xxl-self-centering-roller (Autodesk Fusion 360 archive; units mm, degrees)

design "XXL SELF CENTERING ROLLER" references "XXL ROLLER"
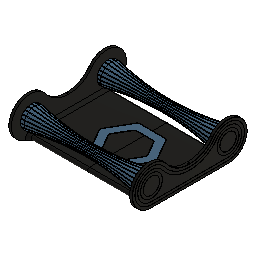
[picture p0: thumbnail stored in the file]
sketch "Sketch1" plane through (0, 0, 0) normal (1, 0, 0) x axis (0, 1, 0)
  line L1 (70, 4) -> (-70, 4)
  line L2 (70, -4) -> (70, 4)
  line L3 (-70, -4) -> (70, -4)
  line L4 (-70, 4) -> (-70, -4)
  line L5 (70, -4) -> (-70, 4)
  line L6 (-70, -4) -> (70, 4)
  line L7 (-110.4145, 0) -> (-90.2073, 35)
  line L8 (-90.2073, -35) -> (-110.4145, 0)
  line L9 (-49.7927, -35) -> (-90.2073, -35)
  line L10 (-29.5855, 0) -> (-49.7927, -35)
  line L11 (-49.7927, 35) -> (-29.5855, 0)
  line L12 (-90.2073, 35) -> (-49.7927, 35)
  line L13 (29.5855, 0) -> (49.7927, 35)
  line L14 (49.7927, -35) -> (29.5855, 0)
  line L15 (90.2073, -35) -> (49.7927, -35)
  line L16 (110.4145, 0) -> (90.2073, -35)
  line L17 (90.2073, 35) -> (110.4145, 0)
  line L18 (49.7927, 35) -> (90.2073, 35)
  line L19 (-49.7927, -35) -> (49.7927, -35)
  line L20 (29.5855, 0) -> (-29.5855, 0)
  line L21 (-85.5885, -27) -> (-90.2073, -35)
  line L22 (85.5885, -27) -> (-85.5885, -27)
  line L23 (90.2073, -35) -> (85.5885, -27)
  line L24 (-94.8261, -27) -> (94.8261, -27)
  line L25 (70, 0) -> (-70, 0)
  line L26 (0, -35) -> (0, 0)
  line L27 (0, -35) -> (0, -27)
  line L28 (-70, -27) -> (70, -27)
  line L29 (70, -35) -> (-70, -35)
  line L30 (70, -31) -> (70, 0)
  circle C1 centre (-70, 0) radius 4
  circle C2 centre (70, 0) radius 4
  circle C3 centre (70, 0) radius 5
  circle C4 centre (-70, 0) radius 5
  circle C5 centre (-70, 0) radius 35
  circle C6 centre (70, 0) radius 35
  arc A1 centre (-70, -31) radius 4 clockwise from (-70, -35) to (-70, -27)
  arc A2 centre (70, -31) radius 4 clockwise from (70, -27) to (70, -35)
  point P6 (0, 0)
  point P1 (0, 0)
  point P7 (-70, 0)
  point P8 (70, 0)
  point P15 (-70, 0)
  point P22 (70, 0)
  point P27 (94.8261, -27)
  point P28 (-94.8261, -27)
  point P29 (-70, 0)
  point P31 (-70, 0)
  point P32 (70, 0)
  point P33 (0, 0)
  point P34 (0, -35)
  point P35 (0, -27)
  point P42 (0, -31)
  point P30 (70, 0)
  point P43 (70, 0)
  point P40 (70, -31)
  point P44 (70, -31)
  point P41 (-70, -31)
  point P4 (70, -4)
  point P5 (-70, -4)
  horizontal L1
  perpendicular L1 L2
  parallel L1 L3
  parallel L2 L4
  coincident L5 P6
  coincident L6 P6
  coincident P1 P6
  midpoint L4 P7
  midpoint L2 P8
  tangent L1 C1
  coincident P7 P15
  coincident P8 P22
  horizontal L12
  horizontal L18
  parallel L15 L22
  parallel L17 L23
  parallel L7 L21
  coincident L16 P27
  coincident L8 P28
  parallel L22 L24
  collinear L22 L24
  concentric C1 C5
  tangent L9 C5
  concentric C2 C6
  tangent L15 C6
  coincident P29 P31
  coincident P22 P32
  coincident P6 P33
  midpoint L19 P34
  midpoint L24 P35
  tangent L28 A1
  tangent A1 L29
  parallel L28 L29
  tangent L29 A2
  tangent L28 A2
  midpoint L27 P42
  coincident P30 P43
  coincident P40 P44
  vertical L30
  collinear L22 L28
  collinear L19 L29
  vertical P29 P41
  dimension "d1" diameter C1 = 8 (= "d2")
  dimension "d2" diameter C2 = 8
  dimension "d3" distance P4 P5 = 140
  dimension "d4" distance L9 L12 = 70
  dimension "d5" distance L15 L18 = 70 (= "d4")
  dimension "d6" distance L19 L22 = 8
  dimension "d13" = 1
  dimension "d14" = 1
extrude "Extrude1" new body sketch "MirrorComponent4" profile of L9 L10 L14 L15 L19 L22 L24 C5 C6 L27 L28 A1 L29 A2 against normal blind 108
extrude "Extrude2" add sketch "MirrorComponent4" profile of L1 L2 L3 L4 C1 C2 L9 L10 L14 L15 L19 L20 L21 L22 L23 C3 C4 L24 C5 C6 L25 L27 L28 A1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 along normal blind 5
fillet "Fillet3" radius 50
extrude "Extrude3" add sketch "MirrorComponent4" profile of L2 L4 C1 C2 against normal blind 6
chamfer "Chamfer1" distance 0.6
sketch "Sketch2" plane through (5, 0, 0) normal (1, 0, 0) x axis (0, 1, 0)
  line L1 (63.8564, -25) -> (-63.8564, -25)
  line L2 (78.5788, -0.5) -> (64.7224, -24.5)
  line L3 (64.7224, 24.5) -> (78.5788, 0.5)
  line L4 (36.1436, 25) -> (63.8564, 25)
  line L5 (21.4212, 0.5) -> (35.2776, 24.5)
  line L6 (-20.5551, 0) -> (20.5551, 0)
  line L7 (-35.2776, 24.5) -> (-21.4212, 0.5)
  line L8 (-63.8564, 25) -> (-36.1436, 25)
  line L9 (-78.5788, 0.5) -> (-64.7224, 24.5)
  line L10 (-64.7224, -24.5) -> (-78.5788, -0.5)
  line L11 (-75.8653, 0) -> (-62.9326, 22.4)
  line L12 (-62.9326, -22.4) -> (-75.8653, 0)
  line L13 (-35.5662, -22.4) -> (-62.9326, -22.4)
  line L14 (62.9326, -22.4) -> (-35.5662, -22.4)
  line L15 (75.8653, 0) -> (62.9326, -22.4)
  line L16 (62.9326, 22.4) -> (75.8653, 0)
  line L17 (37.0674, 22.4) -> (62.9326, 22.4)
  line L18 (23.6728, -0.8) -> (37.0674, 22.4)
  line L19 (-20.5551, -2.6) -> (20.5551, -2.6)
  line L20 (-37.0674, 22.4) -> (-23.6728, -0.8)
  line L21 (-62.9326, 22.4) -> (-37.0674, 22.4)
  line L22 (-73.5559, 0) -> (-61.7779, 20.4)
  line L23 (-61.7779, -20.4) -> (-73.5559, 0)
  line L24 (-35.5662, -20.4) -> (-61.7779, -20.4)
  line L25 (61.7779, -20.4) -> (-35.5662, -20.4)
  line L26 (73.5559, 0) -> (61.7779, -20.4)
  line L27 (61.7779, 20.4) -> (73.5559, 0)
  line L28 (38.2221, 20.4) -> (61.7779, 20.4)
  line L29 (25.4049, -1.8) -> (38.2221, 20.4)
  line L30 (-20.5551, -4.6) -> (20.5551, -4.6)
  line L31 (-38.2221, 20.4) -> (-25.4049, -1.8)
  line L32 (-61.7779, 20.4) -> (-38.2221, 20.4)
  line L33 (70, -35) -> (-70, -35)
  line L34 (-1.2614, 0) -> (1.2614, 0)
  arc A1 centre (-63.8564, -24) radius 1 clockwise from (-63.8564, -25) to (-64.7224, -24.5)
  arc A2 centre (63.8564, -24) radius 1 clockwise from (64.7224, -24.5) to (63.8564, -25)
  arc A3 centre (77.7128, 0) radius 1 clockwise from (78.5788, 0.5) to (78.5788, -0.5)
  arc A4 centre (63.8564, 24) radius 1 clockwise from (63.8564, 25) to (64.7224, 24.5)
  arc A5 centre (36.1436, 24) radius 1 clockwise from (35.2776, 24.5) to (36.1436, 25)
  arc A6 centre (20.5551, 1) radius 1 clockwise from (21.4212, 0.5) to (20.5551, 0)
  arc A7 centre (-20.5551, 1) radius 1 clockwise from (-20.5551, 0) to (-21.4212, 0.5)
  arc A8 centre (-36.1436, 24) radius 1 clockwise from (-36.1436, 25) to (-35.2776, 24.5)
  arc A9 centre (-63.8564, 24) radius 1 clockwise from (-64.7224, 24.5) to (-63.8564, 25)
  arc A10 centre (-77.7128, 0) radius 1 clockwise from (-78.5788, -0.5) to (-78.5788, 0.5)
  arc A11 centre (20.5551, 1) radius 3.6 clockwise from (23.6728, -0.8) to (20.5551, -2.6)
  arc A12 centre (-20.5551, 1) radius 3.6 clockwise from (-20.5551, -2.6) to (-23.6728, -0.8)
  arc A13 centre (20.5551, 1) radius 5.6 clockwise from (25.4049, -1.8) to (20.5551, -4.6)
  arc A14 centre (-20.5551, 1) radius 5.6 clockwise from (-20.5551, -4.6) to (-25.4049, -1.8)
  arc A15 centre (70, 0) radius 35 clockwise from (41.6959, 20.5882) to (70, -35)
  arc A16 centre (-70, 0) radius 35 clockwise from (-70, -35) to (-41.6959, 20.5882)
  arc A17 centre (-1.2614, 50) radius 50 clockwise from (-1.2614, 0) to (-41.6959, 20.5882)
  arc A18 centre (1.2614, 50) radius 50 clockwise from (41.6959, 20.5882) to (1.2614, 0)
  concentric A6 A11
  concentric A7 A12
  tangent A12 L20
  tangent L18 A11
  tangent A11 L19
  tangent L19 A12
  concentric A6 A13
  concentric A7 A14
  tangent A14 L31
  tangent A13 L30
  tangent L29 A13
  tangent L30 A14
sketch "Sketch3" plane through (0, 0, -27) normal (0, 0, 1) x axis (-1, 0, 0)
  line L1 (108, 70) -> (108, -70)
  line L2 (159.9615, 0) -> (133.9808, -45)
  line L3 (133.9808, 45) -> (159.9615, 0)
  line L4 (82.0192, 45) -> (133.9808, 45)
  line L5 (56.0385, 0) -> (82.0192, 45)
  line L6 (82.0192, -45) -> (56.0385, 0)
  line L7 (133.9808, -45) -> (82.0192, -45)
  line L8 (125.3205, 30) -> (142.641, 0)
  line L9 (90.6795, 30) -> (125.3205, 30)
  line L10 (73.359, 0) -> (90.6795, 30)
  line L11 (90.6795, -30) -> (73.359, 0)
  line L12 (125.3205, -30) -> (90.6795, -30)
  line L13 (142.641, 0) -> (125.3205, -30)
  line L14 (108, -70) -> (0, -70)
  line L15 (0, 70) -> (108, 70)
  line L16 (0, -70) -> (0, 70)
  point P12 (108, 0)
  midpoint L1 P12
  horizontal L7
  dimension "d23" distance L4 L7 = 90
  dimension "d24" = -15
extrude "Extrude5" cut sketch "Sketch3" profile of L1 L4 L5 L6 L7 L12 L10 L9 L11 against normal blind 2
fillet "Fillet2" radius 5
extrude "Extrude6" add sketch "MirrorComponent4" profile of L1 L3 C1 C2 C3 C4 against normal blind 1.4
chamfer "Chamfer3" distance 1.4
sketch "Sketch4" plane through (5, 0, 0) normal (1, 0, 0) x axis (0, 1, 0)
  line L1 (70, -35) -> (-70, -35)
  line L2 (-1.2614, 0) -> (1.2614, 0)
  line L3 (-1.2614, -5) -> (1.2614, -5)
  line L4 (70, -30) -> (-70, -30)
  line L5 (-1.2614, -10) -> (1.2614, -10)
  line L6 (70, -25) -> (-70, -25)
  arc A1 centre (-70, 0) radius 35 clockwise from (-70, -35) to (-41.6959, 20.5882)
  arc A2 centre (70, 0) radius 35 clockwise from (41.6959, 20.5882) to (70, -35)
  arc A3 centre (-1.2614, 50) radius 50 clockwise from (-1.2614, 0) to (-41.6959, 20.5882)
  circle C1 centre (-70, 0) radius 15
  circle C2 centre (70, 0) radius 20
  circle C3 centre (-70, 0) radius 20
  circle C4 centre (70, 0) radius 15
  arc A4 centre (1.2614, 50) radius 50 clockwise from (41.6959, 20.5882) to (1.2614, 0)
  arc A5 centre (70, 0) radius 30 clockwise from (45.7393, 17.6471) to (70, -30)
  arc A6 centre (1.2614, 50) radius 55 clockwise from (45.7393, 17.6471) to (1.2614, -5)
  arc A7 centre (-1.2614, 50) radius 55 clockwise from (-1.2614, -5) to (-45.7393, 17.6471)
  arc A8 centre (-70, 0) radius 30 clockwise from (-70, -30) to (-45.7393, 17.6471)
  arc A9 centre (70, 0) radius 25 clockwise from (49.7828, 14.7059) to (70, -25)
  arc A10 centre (1.2614, 50) radius 60 clockwise from (49.7828, 14.7059) to (1.2614, -10)
  arc A11 centre (-1.2614, 50) radius 60 clockwise from (-1.2614, -10) to (-49.7828, 14.7059)
  arc A12 centre (-70, 0) radius 25 clockwise from (-70, -25) to (-49.7828, 14.7059)
  concentric A1 C1
  concentric A2 C2
  concentric C1 C3
  concentric C2 C4
  concentric A2 A9
  concentric A4 A10
  concentric A3 A11
  concentric A1 A12
  tangent A11 A12
  tangent A9 A10
  tangent L5 A11
  tangent A10 L5
  tangent A9 L6
  tangent A12 L6
  dimension "d152" = -5
  dimension "d154" distance C3 A12 = 5
  dimension "d155" distance C1 C3 = 5
  dimension "d156" distance C2 A9 = 5
  dimension "d157" distance C2 C4 = 5
extrude "Extrude10" cut sketch "Sketch4" profile of C1 C2 C3 C4 A8 L3 A6 A7 L4 A5 A12 L5 A10 A11 A9 L6 against normal blind 0.4
chamfer "Chamfer6" distance 0.4
chamfer "Chamfer10" distance 5
mirror "Mirror1" mirrorStitchTolerance 0.1
sketch "Sketch1" plane through (0, 0, -29) normal (0, 0, 1) x axis (-1, 0, 0)
  line L1 (131.094, -45) -> (84.906, -45)
  line L2 (93.5662, -30) -> (122.4338, -30)
  line L3 (74.8024, -2.5) -> (89.2361, -27.5)
  line L4 (89.2361, 27.5) -> (74.8024, 2.5)
  line L5 (122.4338, 30) -> (93.5662, 30)
  line L6 (84.906, 45) -> (131.094, 45)
  line L7 (57.4819, 2.5) -> (80.5759, 42.5)
  line L8 (80.5759, -42.5) -> (57.4819, -2.5)
  line L9 (158.5181, -2.5) -> (135.4241, -42.5)
  line L10 (135.4241, 42.5) -> (158.5181, 2.5)
  line L11 (141.1976, 2.5) -> (126.7639, 27.5)
  line L12 (126.7639, -27.5) -> (141.1976, -2.5)
  line L13 (84.906, 45) -> (131.094, 45)
  line L14 (57.4819, 2.5) -> (80.5759, 42.5)
  line L15 (80.5759, -42.5) -> (57.4819, -2.5)
  line L16 (131.094, -45) -> (84.906, -45)
  line L17 (158.5181, -2.5) -> (135.4241, -42.5)
  line L18 (135.4241, 42.5) -> (158.5181, 2.5)
  line L19 (122.4338, 30) -> (93.5662, 30)
  line L20 (141.1976, 2.5) -> (126.7639, 27.5)
  line L21 (126.7639, -27.5) -> (141.1976, -2.5)
  line L22 (93.5662, -30) -> (122.4338, -30)
  line L23 (74.8024, -2.5) -> (89.2361, -27.5)
  line L24 (89.2361, 27.5) -> (74.8024, 2.5)
  line L25 (57.6551, 2.4) -> (80.7491, 42.4)
  line L26 (80.7491, -42.4) -> (57.6551, -2.4)
  line L27 (131.094, -44.8) -> (84.906, -44.8)
  line L28 (158.3449, -2.4) -> (135.2509, -42.4)
  line L29 (135.2509, 42.4) -> (158.3449, 2.4)
  line L30 (84.906, 44.8) -> (131.094, 44.8)
  line L31 (122.4338, 30.2) -> (93.5662, 30.2)
  line L32 (89.0629, 27.6) -> (74.6292, 2.6)
  line L33 (74.6292, -2.6) -> (89.0629, -27.6)
  line L34 (93.5662, -30.2) -> (122.4338, -30.2)
  line L35 (126.9371, -27.6) -> (141.3708, -2.6)
  line L36 (141.3708, 2.6) -> (126.9371, 27.6)
  line L37 (151.3013, 0) -> (129.6506, -37.5)
  line L38 (129.6506, 37.5) -> (151.3013, 0)
  line L39 (86.3494, 37.5) -> (129.6506, 37.5)
  line L40 (64.6987, 0) -> (86.3494, 37.5)
  line L41 (86.3494, -37.5) -> (64.6987, 0)
  line L42 (129.6506, -37.5) -> (86.3494, -37.5)
  arc A1 centre (84.906, -40) radius 5 clockwise from (84.906, -45) to (80.5759, -42.5)
  arc A2 centre (93.5662, -25) radius 5 clockwise from (93.5662, -30) to (89.2361, -27.5)
  arc A3 centre (79.1325, 0) radius 5 clockwise from (74.8024, -2.5) to (74.8024, 2.5)
  arc A4 centre (93.5662, 25) radius 5 clockwise from (89.2361, 27.5) to (93.5662, 30)
  arc A5 centre (84.906, 40) radius 5 clockwise from (80.5759, 42.5) to (84.906, 45)
  arc A6 centre (61.812, 0) radius 5 clockwise from (57.4819, -2.5) to (57.4819, 2.5)
  arc A7 centre (131.094, -40) radius 5 clockwise from (135.4241, -42.5) to (131.094, -45)
  arc A8 centre (154.188, 0) radius 5 clockwise from (158.5181, 2.5) to (158.5181, -2.5)
  arc A9 centre (131.094, 40) radius 5 clockwise from (131.094, 45) to (135.4241, 42.5)
  arc A10 centre (122.4338, 25) radius 5 clockwise from (122.4338, 30) to (126.7639, 27.5)
  arc A11 centre (136.8675, 0) radius 5 clockwise from (141.1976, 2.5) to (141.1976, -2.5)
  arc A12 centre (122.4338, -25) radius 5 clockwise from (126.7639, -27.5) to (122.4338, -30)
  arc A13 centre (84.906, 40) radius 5 clockwise from (80.5759, 42.5) to (84.906, 45)
  arc A14 centre (61.812, 0) radius 5 clockwise from (57.4819, -2.5) to (57.4819, 2.5)
  arc A15 centre (84.906, -40) radius 5 clockwise from (84.906, -45) to (80.5759, -42.5)
  arc A16 centre (131.094, -40) radius 5 clockwise from (135.4241, -42.5) to (131.094, -45)
  arc A17 centre (154.188, 0) radius 5 clockwise from (158.5181, 2.5) to (158.5181, -2.5)
  arc A18 centre (131.094, 40) radius 5 clockwise from (131.094, 45) to (135.4241, 42.5)
  arc A19 centre (122.4338, 25) radius 5 clockwise from (122.4338, 30) to (126.7639, 27.5)
  arc A20 centre (136.8675, 0) radius 5 clockwise from (141.1976, 2.5) to (141.1976, -2.5)
  arc A21 centre (122.4338, -25) radius 5 clockwise from (126.7639, -27.5) to (122.4338, -30)
  arc A22 centre (93.5662, -25) radius 5 clockwise from (93.5662, -30) to (89.2361, -27.5)
  arc A23 centre (79.1325, 0) radius 5 clockwise from (74.8024, -2.5) to (74.8024, 2.5)
  arc A24 centre (93.5662, 25) radius 5 clockwise from (89.2361, 27.5) to (93.5662, 30)
  arc A25 centre (61.812, 0) radius 4.8 clockwise from (57.6551, -2.4) to (57.6551, 2.4)
  arc A26 centre (84.906, -40) radius 4.8 clockwise from (84.906, -44.8) to (80.7491, -42.4)
  arc A27 centre (131.094, -40) radius 4.8 clockwise from (135.2509, -42.4) to (131.094, -44.8)
  arc A28 centre (154.188, 0) radius 4.8 clockwise from (158.3449, 2.4) to (158.3449, -2.4)
  arc A29 centre (131.094, 40) radius 4.8 clockwise from (131.094, 44.8) to (135.2509, 42.4)
  arc A30 centre (84.906, 40) radius 4.8 clockwise from (80.7491, 42.4) to (84.906, 44.8)
  arc A31 centre (122.4338, 25) radius 5.2 clockwise from (122.4338, 30.2) to (126.9371, 27.6)
  arc A32 centre (93.5662, 25) radius 5.2 clockwise from (89.0629, 27.6) to (93.5662, 30.2)
  arc A33 centre (79.1325, 0) radius 5.2 clockwise from (74.6292, -2.6) to (74.6292, 2.6)
  arc A34 centre (93.5662, -25) radius 5.2 clockwise from (93.5662, -30.2) to (89.0629, -27.6)
  arc A35 centre (122.4338, -25) radius 5.2 clockwise from (126.9371, -27.6) to (122.4338, -30.2)
  arc A36 centre (136.8675, 0) radius 5.2 clockwise from (141.3708, 2.6) to (141.3708, -2.6)
  circle C1 centre (75.524, -18.75) radius 2.5
  circle C2 centre (75.524, 18.75) radius 2.5
  circle C3 centre (140.476, -18.75) radius 2.5
  circle C4 centre (140.476, 18.75) radius 2.5
  circle C5 centre (75.524, -18.75) radius 2.3
  circle C6 centre (75.524, 18.75) radius 2.3
  circle C7 centre (140.476, 18.75) radius 2.3
  circle C8 centre (140.476, -18.75) radius 2.3
  point P116 (75.524, -18.75)
  point P117 (75.524, 18.75)
  point P118 (140.476, -18.75)
  point P119 (140.476, 18.75)
  midpoint L41 P116
  midpoint L40 P117
  coincident L37 P118
  midpoint L38 P119
  midpoint L37 P118
  concentric C1 C5
  concentric C2 C6
  concentric C4 C7
  concentric C3 C8
  dimension "d37" = -0.2
  dimension "d38" = -0.2
  dimension "d53" = -7.5
  dimension "d54" diameter C1 = 5
  dimension "d55" diameter C3 = 5 (= "d54")
  dimension "d56" diameter C2 = 5 (= "d54")
  dimension "d57" diameter C4 = 5 (= "d54")
  dimension "d90" diameter C5 = 4.6
  dimension "d91" diameter C8 = 4.6 (= "d90")
  dimension "d92" diameter C6 = 4.6 (= "d90")
  dimension "d93" diameter C7 = 4.6 (= "d90")
extrude "Extrude7" new body sketch "Sketch1" profile of A30 L27 A28 L28 A27 L25 A26 L30 L29 L26 A29 A25 A36 L32 A35 L35 A34 L33 L36 A33 A32 L31 L34 A31 along normal blind 2
work_plane "WorkPlane1"
split "Split1" bodies "SIDE B"
chamfer "Chamfer4" distance 0.6
extrude "Extrude8" cut sketch "Sketch1" profile of L38 L41 L40 L37 C1 C2 C3 C4 C5 C6 C7 C8 no distance stored
extrude "Extrude9" add sketch "Sketch1" profile of L38 L41 L40 L37 C1 C2 C3 C4 C5 C6 C7 C8 to an object
extrude "Extrude14" sketch "Sketch1" profile of L38 L41 L40 L37 C1 C2 C3 C4 C5 C6 C7 C8 blind -1 from offset -2.5
extrude "Extrude16" cut of existing geometry blind -0.2
chamfer "Chamfer7" distance 0.2
chamfer "Chamfer5" distance 0.4
sketch "Sketch5" plane through (0, 0, -29) normal (0, 0, 1) x axis (-1, 0, 0)
  line L1 (108, -30) -> (108, -45)
  line L2 (93.5662, -30) -> (108, -30)
  line L3 (74.8024, -2.5) -> (89.2361, -27.5)
  line L4 (89.2361, 27.5) -> (74.8024, 2.5)
  line L5 (108, 30) -> (93.5662, 30)
  line L6 (108, 45) -> (108, 30)
  line L7 (84.906, 45) -> (108, 45)
  line L8 (57.4819, 2.5) -> (80.5759, 42.5)
  line L9 (80.5759, -42.5) -> (57.4819, -2.5)
  line L10 (108, -45) -> (84.906, -45)
  line L11 (104, -37.5) -> (108, -37.5)
  line L12 (104, 37.5) -> (108, 37.5)
  line L13 (100, 36.5) -> (108, 36.5)
  line L14 (100, 38.5) -> (100, 36.5)
  line L15 (108, 38.5) -> (100, 38.5)
  line L16 (108, 36.5) -> (108, 38.5)
  line L17 (100, 38.5) -> (108, 36.5)
  line L18 (108, 38.5) -> (100, 36.5)
  line L19 (100, -38.5) -> (108, -38.5)
  line L20 (100, -36.5) -> (100, -38.5)
  line L21 (108, -36.5) -> (100, -36.5)
  line L22 (108, -38.5) -> (108, -36.5)
  line L23 (100, -36.5) -> (108, -38.5)
  line L24 (108, -36.5) -> (100, -38.5)
  circle C1 centre (75.524, -18.75) radius 2.5
  circle C2 centre (75.524, 18.75) radius 2.5
  arc A1 centre (93.5662, -25) radius 5 clockwise from (93.5662, -30) to (89.2361, -27.5)
  arc A2 centre (79.1325, 0) radius 5 clockwise from (74.8024, -2.5) to (74.8024, 2.5)
  arc A3 centre (93.5662, 25) radius 5 clockwise from (89.2361, 27.5) to (93.5662, 30)
  arc A4 centre (84.906, 40) radius 5 clockwise from (80.5759, 42.5) to (84.906, 45)
  arc A5 centre (61.812, 0) radius 5 clockwise from (57.4819, -2.5) to (57.4819, 2.5)
  arc A6 centre (84.906, -40) radius 5 clockwise from (84.906, -45) to (80.5759, -42.5)
  circle C3 centre (104, 37.5) radius 2
  circle C4 centre (104, -37.5) radius 2
  point P26 (108, -37.5)
  point P28 (108, 37.5)
  point P29 (104, 37.5)
  point P30 (104, 37.5)
  point P35 (104, 37.5)
  point P31 (108, 36.5)
  point P27 (104, -37.5)
  point P36 (104, -37.5)
  point P41 (104, -37.5)
  point P37 (108, -38.5)
  point P38 (100, -38.5)
  point P39 (100, -36.5)
  midpoint L1 P26
  perpendicular L1 L11
  midpoint L6 P28
  perpendicular L6 L12
  coincident P29 P30
  horizontal L13
  perpendicular L13 L14
  parallel L13 L15
  parallel L14 L16
  coincident L17 P35
  coincident L18 P35
  coincident L6 P31
  coincident P30 P35
  coincident P27 P36
  horizontal L19
  perpendicular L19 L20
  parallel L19 L21
  parallel L20 L22
  coincident L23 P41
  coincident L24 P41
  coincident L1 P37
  coincident P36 P41
  dimension "d73" diameter C3 = 4
  dimension "d74" distance L13 L15 = 2
  dimension "d75" distance P28 P29 = 4
  dimension "d76" diameter C4 = 4 (= "d73")
  dimension "d77" distance P37 P38 = 8
  dimension "d78" distance P38 P39 = 2
offset_faces "OffsetFaces2" distance -0.1
combine "Combine1"
offset_faces "OffsetFaces3" distance -0.05
sketch "Sketch8" plane through (0, 0, -34.8) normal (0, 0, -1) x axis (1, 0, 0)
  circle C1 centre (-83.9808, -15) radius 1.8
  circle C2 centre (-32.0192, -15) radius 1.5
  circle C3 centre (-32.0192, 15) radius 1.5
  circle C4 centre (-83.9808, 15) radius 1.5
  circle C5 centre (-83.9808, -15) radius 1.5
  circle C6 centre (-75.524, -18.75) radius 2
  point P5 (-83.9808, 15)
  point P7 (-83.9808, 15)
  point P4 (-32.0192, 15)
  point P8 (-32.0192, 15)
  point P3 (-32.0192, -15)
  point P9 (-32.0192, -15)
  concentric C1 C5
  coincident P5 P7
  coincident P4 P8
  coincident P3 P9
  dimension "d100" diameter C5 = 3
  dimension "d101" diameter C4 = 3 (= "d100")
  dimension "d102" diameter C3 = 3 (= "d101")
  dimension "d103" diameter C2 = 3 (= "d101")
sketch "Sketch9" plane through (-108, 0, 0) normal (1, 0, 0) x axis (0, 1, 0)
  line L1 (30, -29) -> (45, -29)
  line L2 (-45, -27) -> (-45, -29)
  line L3 (-70, -27) -> (-45, -27)
  line L4 (70, -35) -> (-70, -35)
  line L5 (45, -27) -> (70, -27)
  line L6 (45, -29) -> (45, -27)
  line L7 (30, -27) -> (30, -29)
  line L8 (-30, -27) -> (30, -27)
  line L9 (-30, -29) -> (-30, -27)
  line L10 (74, -31) -> (-74, -31)
  line L11 (-61.5, -32) -> (-66.5, -32)
  line L12 (-66.5, -30) -> (-61.5, -30)
  line L13 (-61.5, -31) -> (-66.5, -31)
  line L14 (2.5, -32) -> (-2.5, -32)
  line L15 (-2.5, -30) -> (2.5, -30)
  line L16 (2.5, -31) -> (-2.5, -31)
  line L17 (66.5, -32) -> (61.5, -32)
  line L18 (61.5, -30) -> (66.5, -30)
  line L19 (66.5, -31) -> (61.5, -31)
  line L20 (-45, -29) -> (-30, -29)
  arc A1 centre (-70, -31) radius 4 clockwise from (-70, -35) to (-70, -27)
  arc A2 centre (70, -31) radius 4 clockwise from (70, -27) to (70, -35)
  circle C1 centre (-64, -31) radius 0.9
  circle C2 centre (0, -31) radius 0.9
  circle C3 centre (64, -31) radius 0.9
  arc A3 centre (-61.5, -31) radius 1 clockwise from (-61.5, -30) to (-61.5, -32)
  arc A4 centre (-66.5, -31) radius 1 clockwise from (-66.5, -32) to (-66.5, -30)
  arc A5 centre (2.5, -31) radius 1 clockwise from (2.5, -30) to (2.5, -32)
  arc A6 centre (-2.5, -31) radius 1 clockwise from (-2.5, -32) to (-2.5, -30)
  arc A7 centre (66.5, -31) radius 1 clockwise from (66.5, -30) to (66.5, -32)
  arc A8 centre (61.5, -31) radius 1 clockwise from (61.5, -32) to (61.5, -30)
  point P20 (-74, -31)
  point P21 (74, -31)
  point P19 (64, -31)
  point P18 (0, -31)
  point P17 (-64, -31)
  point P27 (-61.5, -31)
  point P28 (-64, -31)
  point P34 (2.5, -31)
  point P35 (0, -31)
  point P41 (66.5, -31)
  point P42 (64, -31)
  point P26 (-66.5, -31)
  point P40 (61.5, -31)
  point P33 (-2.5, -31)
  midpoint A1 P20
  midpoint A2 P21
  coincident P19 L10
  coincident P18 L10
  coincident P17 L10
  midpoint P18 L10
  tangent L11 A3
  tangent A3 L12
  parallel L11 L12
  tangent L12 A4
  tangent L11 A4
  coincident L10 P27
  parallel L10 L13
  coincident P17 P28
  midpoint L13 P28
  tangent L14 A5
  tangent A5 L15
  parallel L14 L15
  tangent L15 A6
  tangent L14 A6
  coincident L10 P34
  parallel L10 L16
  coincident P18 P35
  midpoint L16 P35
  tangent L17 A7
  tangent A7 L18
  parallel L17 L18
  tangent L18 A8
  tangent L17 A8
  coincident L10 P41
  parallel L10 L19
  coincident P19 P42
  midpoint L19 P42
  dimension "d108" diameter C1 = 1.8
  dimension "d109" diameter C2 = 1.8
  dimension "d110" diameter C3 = 1.8
  dimension "d111" distance P17 P20 = 10
  dimension "d112" distance P19 P21 = 10
  dimension "d115" distance L11 L12 = 2
  dimension "d116" distance P26 P27 = 5
  dimension "d117" distance P40 P41 = 5
  dimension "d118" distance L17 L18 = 2
  dimension "d119" distance L14 L15 = 2
  dimension "d120" distance P33 P34 = 5
extrude "Extrude17" cut sketch "Sketch9" profile of C1 C2 C3 L10 L11 A3 L12 A4 L14 A5 L15 A6 L17 A7 L18 A8 distance -20
sketch "Sketch10" plane through (-108, 0, 0) normal (1, 0, 0) x axis (0, 1, 0)
  line L1 (2.5, -32) -> (-2.5, -32)
  line L2 (-2.5, -30) -> (2.5, -30)
  line L3 (66.5, -32) -> (61.5, -32)
  line L4 (61.5, -30) -> (66.5, -30)
  line L5 (-61.5, -32) -> (-66.5, -32)
  line L6 (-66.5, -30) -> (-61.5, -30)
  line L7 (-45, -29) -> (-45, -27)
  line L8 (-30, -29) -> (-45, -29)
  line L9 (-30, -27) -> (-30, -29)
  line L10 (30, -27) -> (-30, -27)
  line L11 (30, -29) -> (30, -27)
  line L12 (45, -29) -> (30, -29)
  line L13 (45, -27) -> (45, -29)
  line L14 (70, -27) -> (45, -27)
  line L15 (-70, -35) -> (70, -35)
  line L16 (-45, -27) -> (-70, -27)
  line L17 (66.5, -31.8) -> (61.5, -31.8)
  line L18 (61.5, -30.2) -> (66.5, -30.2)
  line L19 (-2.5, -30.2) -> (2.5, -30.2)
  line L20 (2.5, -31.8) -> (-2.5, -31.8)
  line L21 (-66.5, -30.2) -> (-61.5, -30.2)
  line L22 (-61.5, -31.8) -> (-66.5, -31.8)
  arc A1 centre (2.5, -31) radius 1 clockwise from (2.5, -30) to (2.5, -32)
  arc A2 centre (-2.5, -31) radius 1 clockwise from (-2.5, -32) to (-2.5, -30)
  arc A3 centre (66.5, -31) radius 1 clockwise from (66.5, -30) to (66.5, -32)
  arc A4 centre (61.5, -31) radius 1 clockwise from (61.5, -32) to (61.5, -30)
  arc A5 centre (-61.5, -31) radius 1 clockwise from (-61.5, -30) to (-61.5, -32)
  arc A6 centre (-66.5, -31) radius 1 clockwise from (-66.5, -32) to (-66.5, -30)
  arc A7 centre (70, -31) radius 4 clockwise from (70, -27) to (70, -35)
  arc A8 centre (-70, -31) radius 4 clockwise from (-70, -35) to (-70, -27)
  arc A9 centre (66.5, -31) radius 0.8 clockwise from (66.5, -30.2) to (66.5, -31.8)
  arc A10 centre (61.5, -31) radius 0.8 clockwise from (61.5, -31.8) to (61.5, -30.2)
  arc A11 centre (2.5, -31) radius 0.8 clockwise from (2.5, -30.2) to (2.5, -31.8)
  arc A12 centre (-2.5, -31) radius 0.8 clockwise from (-2.5, -31.8) to (-2.5, -30.2)
  arc A13 centre (-66.5, -31) radius 0.8 clockwise from (-66.5, -31.8) to (-66.5, -30.2)
  arc A14 centre (-61.5, -31) radius 0.8 clockwise from (-61.5, -30.2) to (-61.5, -31.8)
  dimension "d130" = -0.2
  dimension "d131" = -0.2 (= "d130")
  dimension "d132" = -0.2 (= "d130")
extrude "Extrude18" new body sketch "Sketch10" profile of A14 A13 L22 L21 distance -19 bodies "INTERNAL SUPPORT"
chamfer "Chamfer8" distance 0.5
chamfer "Chamfer9" distance 0.6
rectangular_pattern "R-Pattern1" uSpaceDistance -128 vSpaceDistance 0 bodies "INTERNAL SUPPORT (1)", "INTERNAL SUPPORT (2)"
component_insert "Component Insert"
joint "Assemble5" alignAngle 0 alignOffsetX 0 alignOffsetY 0 alignOffsetZ 0
mirror_component "MirrorComponent4"
derived_instance "DerivedInstance4"
derived_instance "DerivedInstance1"
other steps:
derived_base_feature "Derived Base Feature1"
derived_base_feature "Derived Base Feature1"
create_component "CreateComponent3"
joint_origin "JointOrigin6"
create_component "CreateComponent10"
create_component "CreateComponent11"
named bodies: "SIDE A", "HEX INSERT", "SIDE B", "INTERNAL SUPPORT", "INTERNAL SUPPORT (1)", "INTERNAL SUPPORT (2)"

design "Bearing"
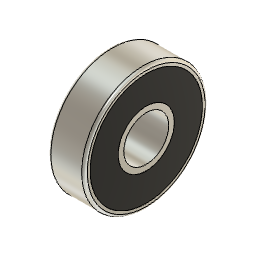
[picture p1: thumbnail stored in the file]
base_feature "Base Feature"
sketch "Sketch1" plane through (11, 0, 0) normal (1, 0, 0) x axis (0, 0, -1)
  circle C1 centre (0, 111) radius 4
  circle C2 centre (0, 111) radius 5
  circle C3 centre (0, 111) radius 4
  circle C4 centre (0, 111) radius 11
  concentric C1 C3
  concentric C3 C4
  dimension "d121" diameter C4 = 22
  dimension "d122" diameter C3 = 8
extrude "Extrude1" new body sketch "Sketch1" along normal blind 6.5
fillet "Fillet1" radius 0.5
sketch "Sketch2" plane through (17.5, 0, 0) normal (1, 0, 0) x axis (0, 1, 0)
  circle C1 centre (111, 0) radius 4
  circle C2 centre (111, 0) radius 10.5
  circle C3 centre (111, 0) radius 10
  circle C4 centre (111, 0) radius 5
  concentric C1 C3
  concentric C3 C4
  dimension "d3" distance C1 C4 = 1
  dimension "d4" distance C2 C3 = 0.5
extrude "Extrude2" cut sketch "Sketch2" profile of C3 C4 against normal blind 6.5
extrude "Extrude3" new body sketch "Sketch2" profile of C3 C4 against normal blind 6.5

design "XXL ROLLER" references "Bearing"
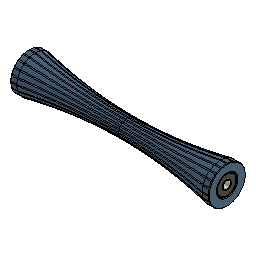
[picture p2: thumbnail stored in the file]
sketch "Sketch2" plane through (0, 0, 0) normal (0, 0, 1) x axis (1, 0, 0)
  line L1 (100, 20) -> (-100, 20)
  line L2 (100, -20) -> (100, 20)
  line L3 (-100, -20) -> (100, -20)
  line L4 (-100, 20) -> (-100, -20)
  line L5 (100, -20) -> (-100, 20)
  line L6 (-100, -20) -> (100, 20)
  line L7 (-107, 20) -> (-100, 20)
  line L8 (-107, 11.05) -> (-107, 20)
  line L9 (-100, 11.05) -> (-107, 11.05)
  line L10 (-100, 20) -> (-100, 11.05)
  line L11 (-100, 0) -> (0, 0)
  line L12 (100, 0) -> (-100, 0)
  line L13 (0, 20) -> (0, 0)
  line L14 (-98, 0) -> (-100, 0)
  line L15 (-98, 7) -> (-98, 0)
  line L16 (-100, 7) -> (-98, 7)
  line L17 (-100, 0) -> (-100, 7)
  arc A1 centre (0, 509.8979) radius 500 clockwise from (100, 20) to (-100, 20)
  point P6 (0, 0)
  point P1 (0, 0)
  point P10 (0, 0)
  point P11 (-100, 0)
  point P13 (100, 0)
  point P14 (0, 0)
  point P15 (0, 20)
  point P2 (-100, 20)
  point P7 (-107, 20)
  point P16 (-98, 0)
  point P17 (-98, 7)
  point P18 (-100, 7)
  horizontal L1
  perpendicular L1 L2
  parallel L1 L3
  parallel L2 L4
  coincident L5 P6
  coincident L6 P6
  coincident P1 P6
  horizontal L7
  vertical L8
  horizontal L9
  vertical L10
  coincident P6 P10
  midpoint L4 P11
  midpoint L2 P13
  coincident P1 P14
  midpoint L1 P15
  horizontal L14
  vertical L15
  horizontal L16
  vertical L17
  dimension "d2" distance P10 P11 = 100
  dimension "d3" distance L9 P11 = 11.05
  dimension "d4" distance L1 L3 = 40
  dimension "d5" radius A1 = 500
  dimension "d6" distance P2 P7 = 7
  dimension "d26" distance P16 P17 = 7
  dimension "d27" distance P17 P18 = 2
revolve "Revolve1" sketch "Sketch2" AlongAngle 360
mirror "Mirror1" mirrorStitchTolerance 0.1
component_insert "Component Insert1"
joint "Assemble1" alignAngle 0 alignOffsetX 0 alignOffsetY 0 alignOffsetZ 0
component_insert "Component Insert2"
joint "Assemble2" alignAngle 0 alignOffsetX 0 alignOffsetY 0 alignOffsetZ 0
chamfer "Chamfer1" distance 0.6
sketch "Sketch3" plane through (100, 0, 0) normal (1, 0, 0) x axis (0, 1, 0)
  line L1 (7, -8.55) -> (-7, -8.55)
  line L2 (7, 8.55) -> (7, -8.55)
  line L3 (-7, 8.55) -> (7, 8.55)
  line L4 (-7, -8.55) -> (-7, 8.55)
  line L5 (7, 8.55) -> (-7, -8.55)
  line L6 (-7, 8.55) -> (7, -8.55)
  line L7 (8.55, -7) -> (-8.55, -7)
  line L8 (8.55, 7) -> (8.55, -7)
  line L9 (-8.55, 7) -> (8.55, 7)
  line L10 (-8.55, -7) -> (-8.55, 7)
  line L11 (8.55, 7) -> (-8.55, -7)
  line L12 (-8.55, 7) -> (8.55, -7)
  circle C1 centre (0, 0) radius 7
  circle C2 centre (0, 0) radius 11.05
  circle C3 centre (0, 0) radius 7
  point P7 (0, 0)
  point P3 (-7, -8.55)
  point P2 (0, 0)
  point P12 (0, 0)
  point P8 (-8.55, -7)
  horizontal L1
  perpendicular L1 L2
  parallel L1 L3
  parallel L2 L4
  coincident L5 P7
  coincident L6 P7
  coincident C2 P3
  coincident P2 P7
  horizontal L7
  perpendicular L7 L8
  parallel L7 L9
  parallel L8 L10
  coincident L11 P12
  coincident L12 P12
  coincident C2 P8
  coincident P7 P12
  tangent C1 L2
  tangent L7 C3
extrude "Extrude2" cut sketch "Sketch3" profile of C1 C2 L1 L2 L3 L4 L7 L9 C3 against normal blind 0.2
extrude "Extrude3" cut sketch "Sketch3" profile of C1 L2 L4 L7 L9 C3 against normal blind 0.4
chamfer "Chamfer2" distance 1.6
split "Split1"
sketch "Sketch1" plane through (0, 0, 0) normal (1, 0, 0) x axis (0, 1, 0)
  line L1 (5.7735, 0) -> (2.8868, -5)
  line L2 (2.8868, 5) -> (5.7735, 0)
  line L3 (-2.8868, 5) -> (2.8868, 5)
  line L4 (-5.7735, 0) -> (-2.8868, 5)
  line L5 (-2.8868, -5) -> (-5.7735, 0)
  line L6 (2.8868, -5) -> (-2.8868, -5)
  line L7 (2.829, 4.9) -> (5.658, 0)
  line L8 (-2.829, 4.9) -> (2.829, 4.9)
  line L9 (-5.658, 0) -> (-2.829, 4.9)
  line L10 (-2.829, -4.9) -> (-5.658, 0)
  line L11 (2.829, -4.9) -> (-2.829, -4.9)
  line L12 (5.658, 0) -> (2.829, -4.9)
  point P1 (0, 0)
  point P8 (0, 0)
  coincident P1 P8
  horizontal L6
  dimension "d19" distance L1 L4 = 10
  dimension "d20" = -0.1
extrude "Extrude1" cut sketch "Sketch1" distance -30
extrude "Extrude1" new body sketch "Sketch1" profile of L12 L11 L10 L9 L8 L7 distance 29
chamfer "Chamfer1" distance 0.6
ground "Ground1"
component_from_bodies "Body->Comp"
as_built_joint "As-built1"
sketch "Sketch2" plane through (0, 0, 0) normal (0, 1, 0) x axis (1, 0, 0)
  line L1 (100, 20) -> (100, -20)
  line L2 (0, 9.8979) -> (0, -9.8979)
  line L3 (100, 20) -> (100, -20)
  line L4 (106.4, 20) -> (106.4, -20)
  line L5 (106.4, 20) -> (106.4, -20)
  line L6 (107, -19.4) -> (107, 19.4)
  line L7 (-100, -20) -> (-106.4, -20)
  line L8 (-106.4, 20) -> (-100, 20)
  line L9 (-107, 19.4) -> (-106.4, 20)
  line L10 (-106.4, -20) -> (-107, -19.4)
  line L11 (106.4, 20) -> (107, 19.4)
  line L12 (107, -19.4) -> (106.4, -20)
  line L13 (106.4, -20) -> (100, -20)
  line L14 (100, 20) -> (106.4, 20)
  line L15 (111.4, -20) -> (106.4, -20)
  line L16 (-111.4, -20) -> (-106.4, -20)
  arc A1 centre (0, -509.8979) radius 500 between (100, -20) and (0, -9.8979)
  arc A2 centre (0, 509.8979) radius 500 between (0, 9.8979) and (100, 20)
  arc A3 centre (0, -509.8979) radius 500 between (0, -9.8979) and (-100, -20)
  arc A4 centre (0, 509.8979) radius 500 between (-100, 20) and (0, 9.8979)
  point P8 (106.4, -20)
  point P42 (106.4, -20)
  point P33 (-106.4, -20)
  point P44 (-106.4, -20)
  point P43 (111.4, -20)
  point P45 (-111.4, -20)
  coincident P8 P42
  perpendicular L4 L15
  coincident P33 P44
  parallel L7 L16
  dimension "d29" distance P42 P43 = 5
  dimension "d40" distance P44 P45 = 5 (= "d29")
pipe "Pipe1" SectionSize 1.2 SectionThickness 0.3
circular_pattern "C-Pattern1" countU 20 TotalAngle 360
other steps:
base_feature "Base Feature"
create_component "CreateComponent1"
joint_origin "JointOrigin1"
joint_origin "JointOrigin2"
create_component "CreateComponent3"
remove_body "RemoveBody1"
